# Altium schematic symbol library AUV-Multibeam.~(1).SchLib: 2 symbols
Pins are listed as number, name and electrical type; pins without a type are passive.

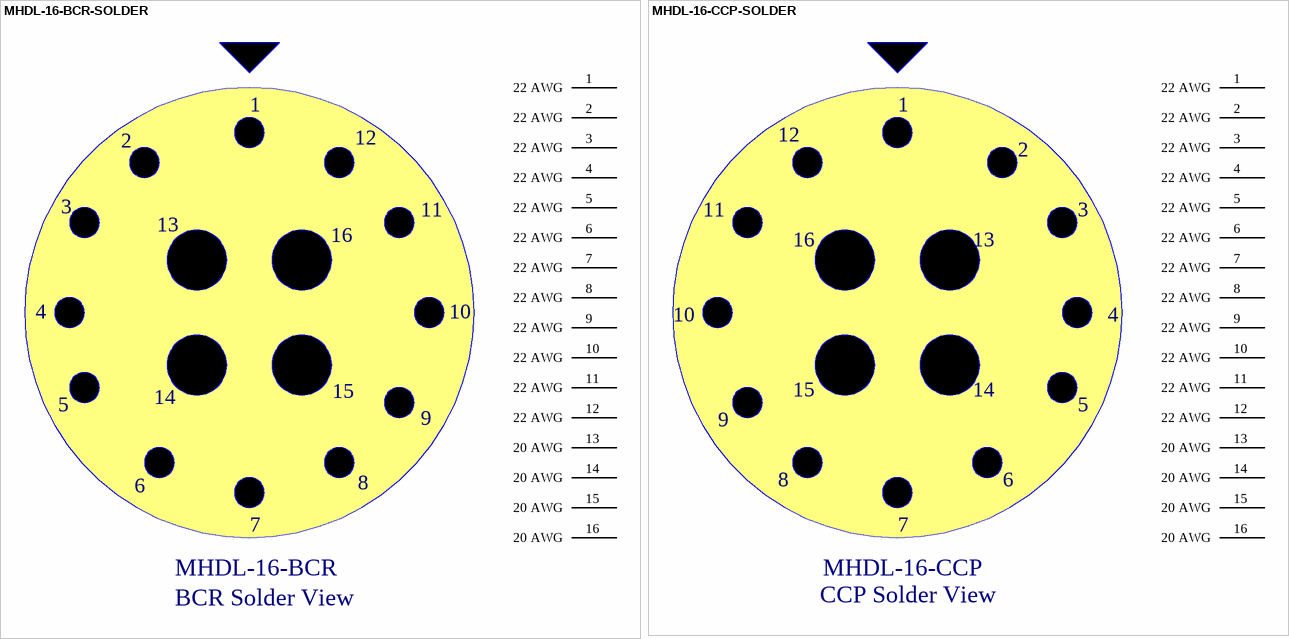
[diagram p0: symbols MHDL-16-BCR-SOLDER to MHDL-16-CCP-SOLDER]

## MHDL-16-BCR-SOLDER
designator J?, comment MHDL-16-BCR
Impulse MHDL 16 BCR
pins: 1 22 AWG, 2 22 AWG, 3 22 AWG, 4 22 AWG, 5 22 AWG, 6 22 AWG, 7 22 AWG, 8 22 AWG, 9 22 AWG, 10 22 AWG, 11 22 AWG, 12 22 AWG, 13 20 AWG, 14 20 AWG, 15 20 AWG, 16 20 AWG

## MHDL-16-CCP-SOLDER
designator J?, comment MHDL-16-CCP
Impulse MHDL 16 CCP
pins: 1 22 AWG, 2 22 AWG, 3 22 AWG, 4 22 AWG, 5 22 AWG, 6 22 AWG, 7 22 AWG, 8 22 AWG, 9 22 AWG, 10 22 AWG, 11 22 AWG, 12 22 AWG, 13 20 AWG, 14 20 AWG, 15 20 AWG, 16 20 AWG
